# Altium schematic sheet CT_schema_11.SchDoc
size 387 x 385 mm
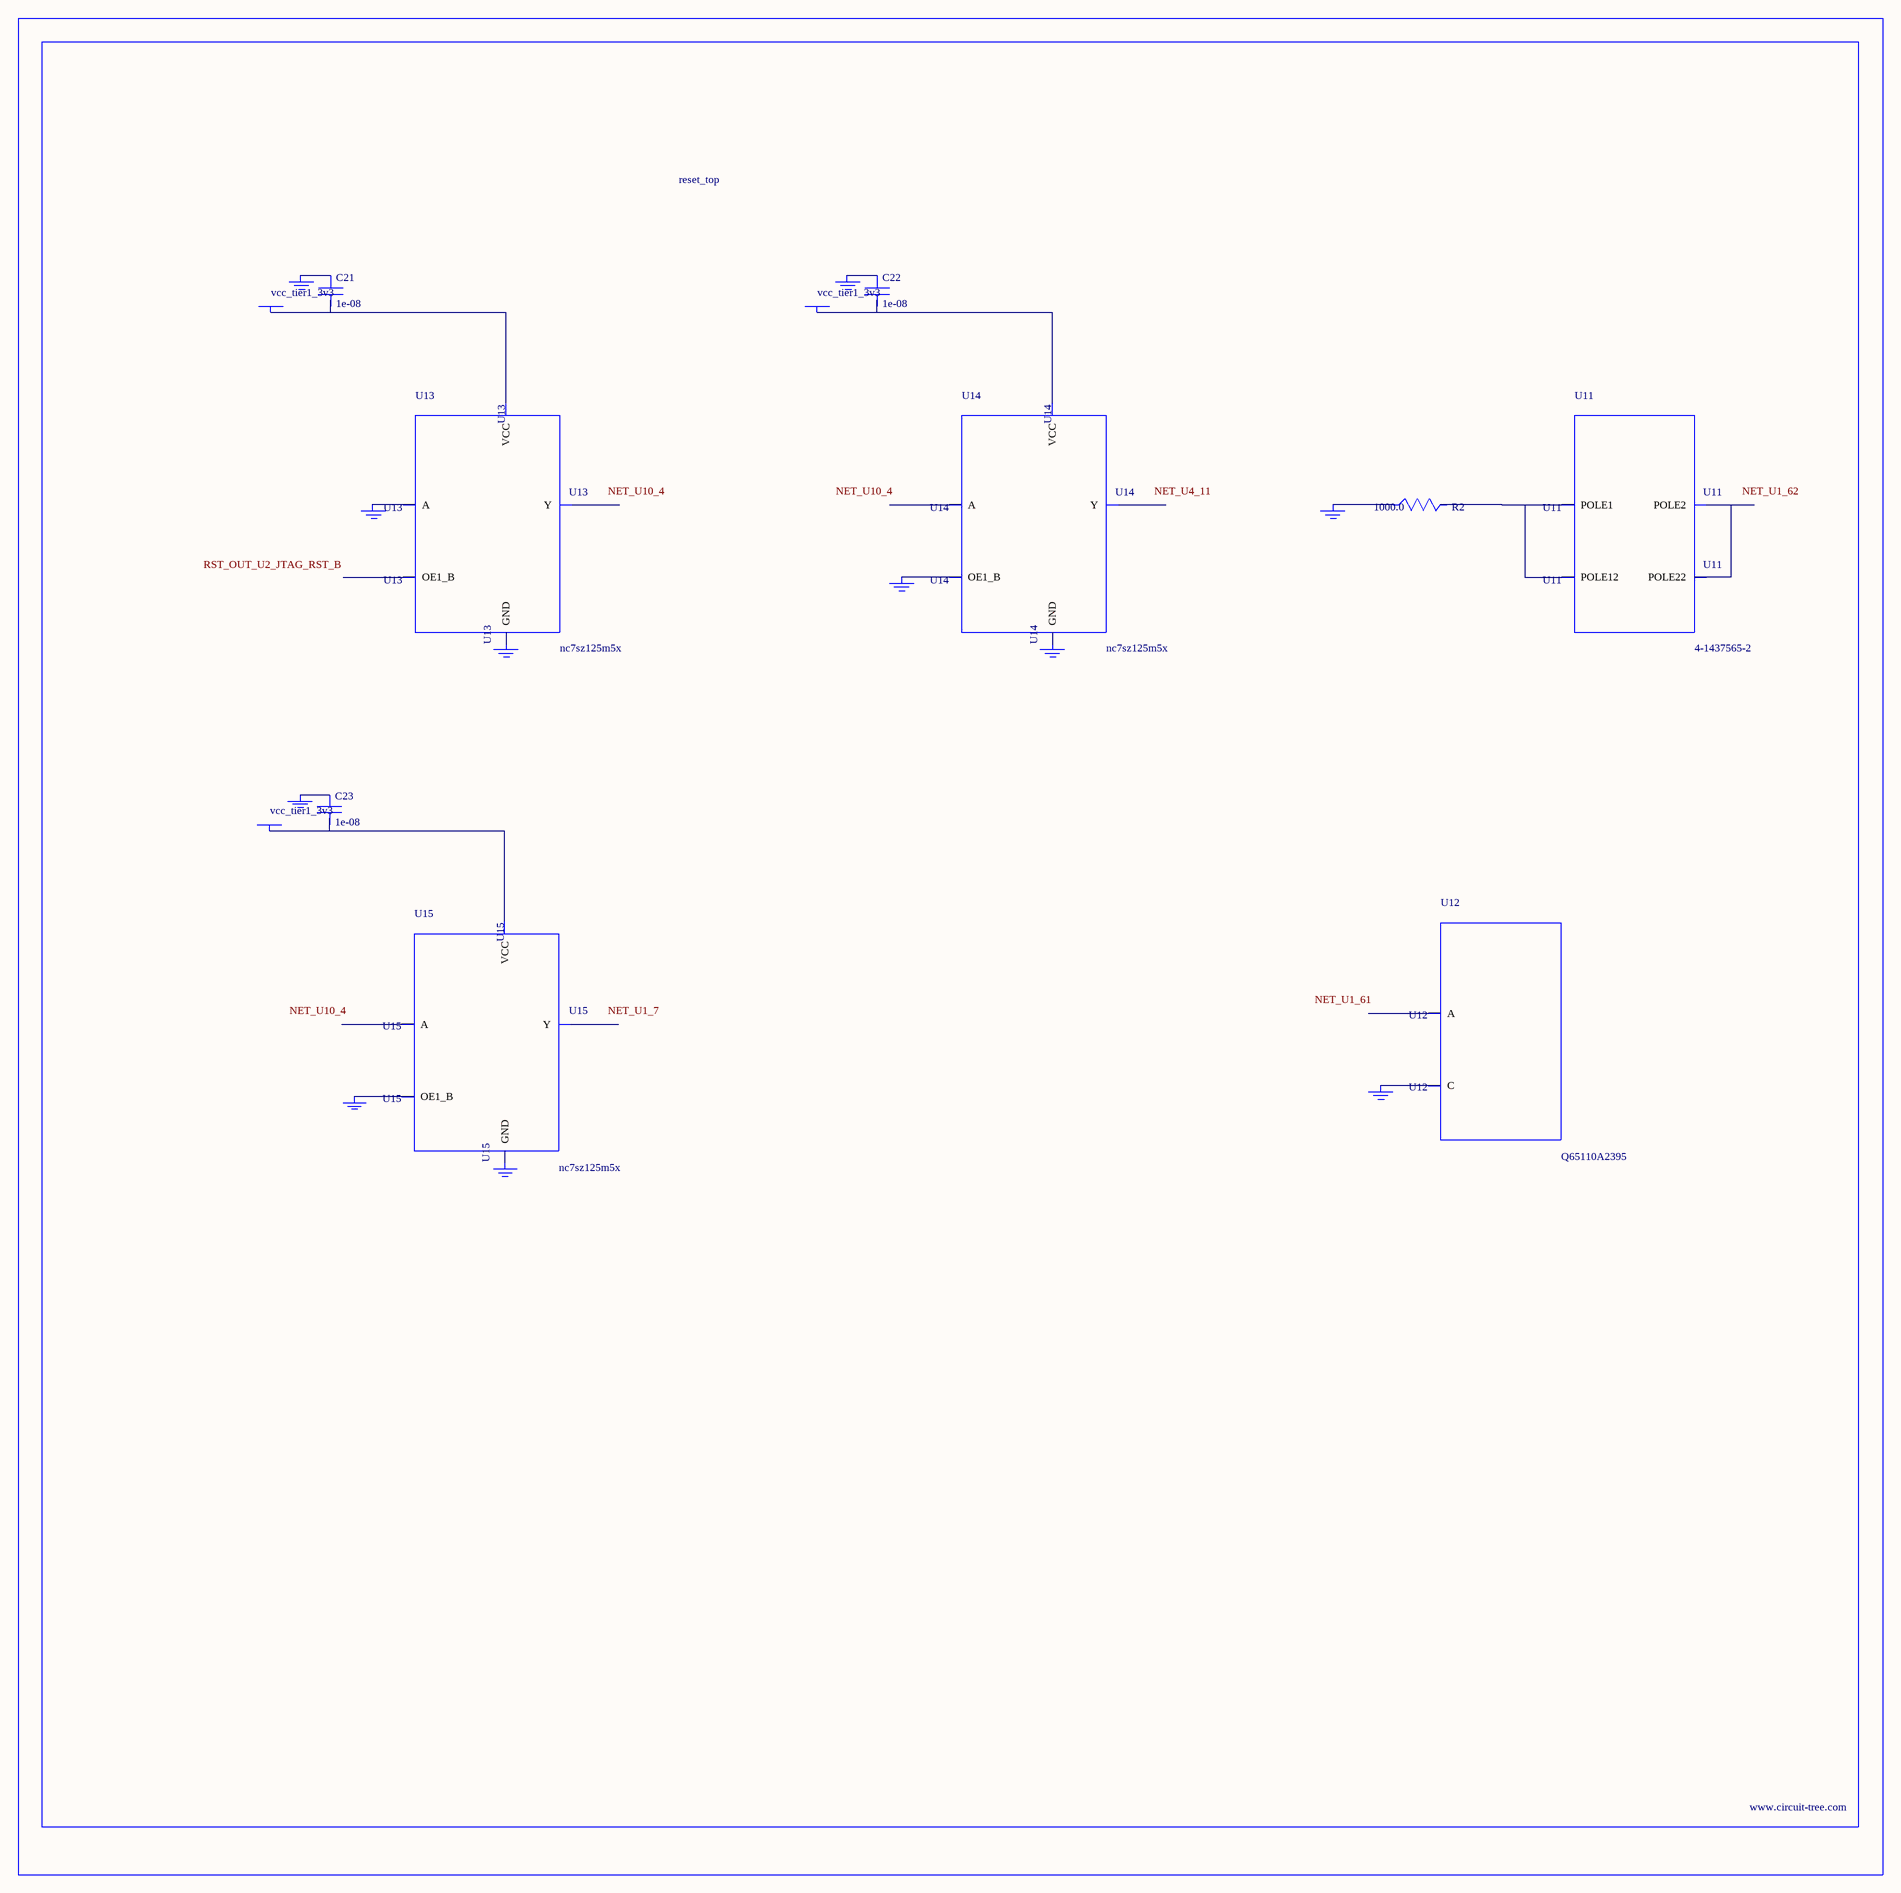
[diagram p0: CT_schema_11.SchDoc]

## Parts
BORDER10  (no value)
C21  1e-08  [C0402]
C22  1e-08  [C0402]
C23  1e-08  [C0402]
GND_INSTANCE_10_0  (no value)
GND_INSTANCE_10_1  (no value)
GND_INSTANCE_10_2  (no value)
GND_INSTANCE_10_3  (no value)
GND_INSTANCE_10_4  (no value)
GND_INSTANCE_10_5  (no value)
GND_INSTANCE_10_6  (no value)
GND_INSTANCE_10_7  (no value)
GND_INSTANCE_10_8  (no value)
GND_INSTANCE_10_9  (no value)
GND_INSTANCE_10_10  (no value)
POWER_INSTANCE_10_0  vcc_tier1_3v3
POWER_INSTANCE_10_1  vcc_tier1_3v3
POWER_INSTANCE_10_2  vcc_tier1_3v3
R2  1000.0  [R0603]
U11  4-1437565-2  [SW_4-1437565-2]
U12  Q65110A2395  [LGM67K-G1J2-24-Z]
U13  nc7sz125m5x  [NC7SZ125M5X]
U14  nc7sz125m5x  [NC7SZ125M5X]
U15  nc7sz125m5x  [NC7SZ125M5X]

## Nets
NetC21_1: C21.1 GND_INSTANCE_10_2.0(GND)
NetC21_2: C21.2 POWER_INSTANCE_10_0.0(PWR) U13.5(VCC)
NetC22_1: C22.1 GND_INSTANCE_10_5.0(GND)
NetC22_2: C22.2 POWER_INSTANCE_10_1.0(PWR) U14.5(VCC)
NetC23_1: C23.1 GND_INSTANCE_10_8.0(GND)
NetC23_2: C23.2 POWER_INSTANCE_10_2.0(PWR) U15.5(VCC)
NetGND_INSTANCE_10_0_0: GND_INSTANCE_10_0.0(GND) R2.1
NetGND_INSTANCE_10_1_0: GND_INSTANCE_10_1.0(GND) U12.C
NetGND_INSTANCE_10_3_0: GND_INSTANCE_10_3.0(GND) U13.2(A)
NetGND_INSTANCE_10_4_0: GND_INSTANCE_10_4.0(GND) U13.3(GND)
NetGND_INSTANCE_10_6_0: GND_INSTANCE_10_6.0(GND) U14.1(OE1_B)
NetGND_INSTANCE_10_7_0: GND_INSTANCE_10_7.0(GND) U14.3(GND)
NetGND_INSTANCE_10_9_0: GND_INSTANCE_10_9.0(GND) U15.1(OE1_B)
NetGND_INSTANCE_10_10_0: GND_INSTANCE_10_10.0(GND) U15.3(GND)
NetR2_2: R2.2 U11.1(POLE1) U11.2(POLE12)
NetU11_3: U11.3(POLE2) U11.4(POLE22)

Not connected (* = marked no-connect by the designer): U12 A; U13 1(OE1_B) 4(Y); U14 2(A) 4(Y); U15 2(A) 4(Y)

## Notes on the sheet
- Labels drawn without touching a wire or pin: NET_U1_7, NET_U1_61, NET_U1_62, NET_U4_11, NET_U10_4, RST_OUT_U2_JTAG_RST_B

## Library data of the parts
BORDER10 = BORDER_PAGE10
C21-C23 = C0402C103K3RAC
GND_INSTANCE_10_0-GND_INSTANCE_10_10 = GND
POWER_INSTANCE_10_0-POWER_INSTANCE_10_2 = PWR
R2 = RC0603JR-071KL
